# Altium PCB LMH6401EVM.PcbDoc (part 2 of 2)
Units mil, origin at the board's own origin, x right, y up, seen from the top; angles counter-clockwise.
Board outline 1307 x 2660 mil, 6 copper layers (Top Layer L1, Layer 2 GND L2, Layer 3 V+ L3, Layer 4 V- L4, Layer 5 GND L5, Bottom Layer L6), stack 56.6 mil thick; 69 components, 33 nets, 203 pads, 373 vias.
Unrouted connection lines stored in the file: 2.
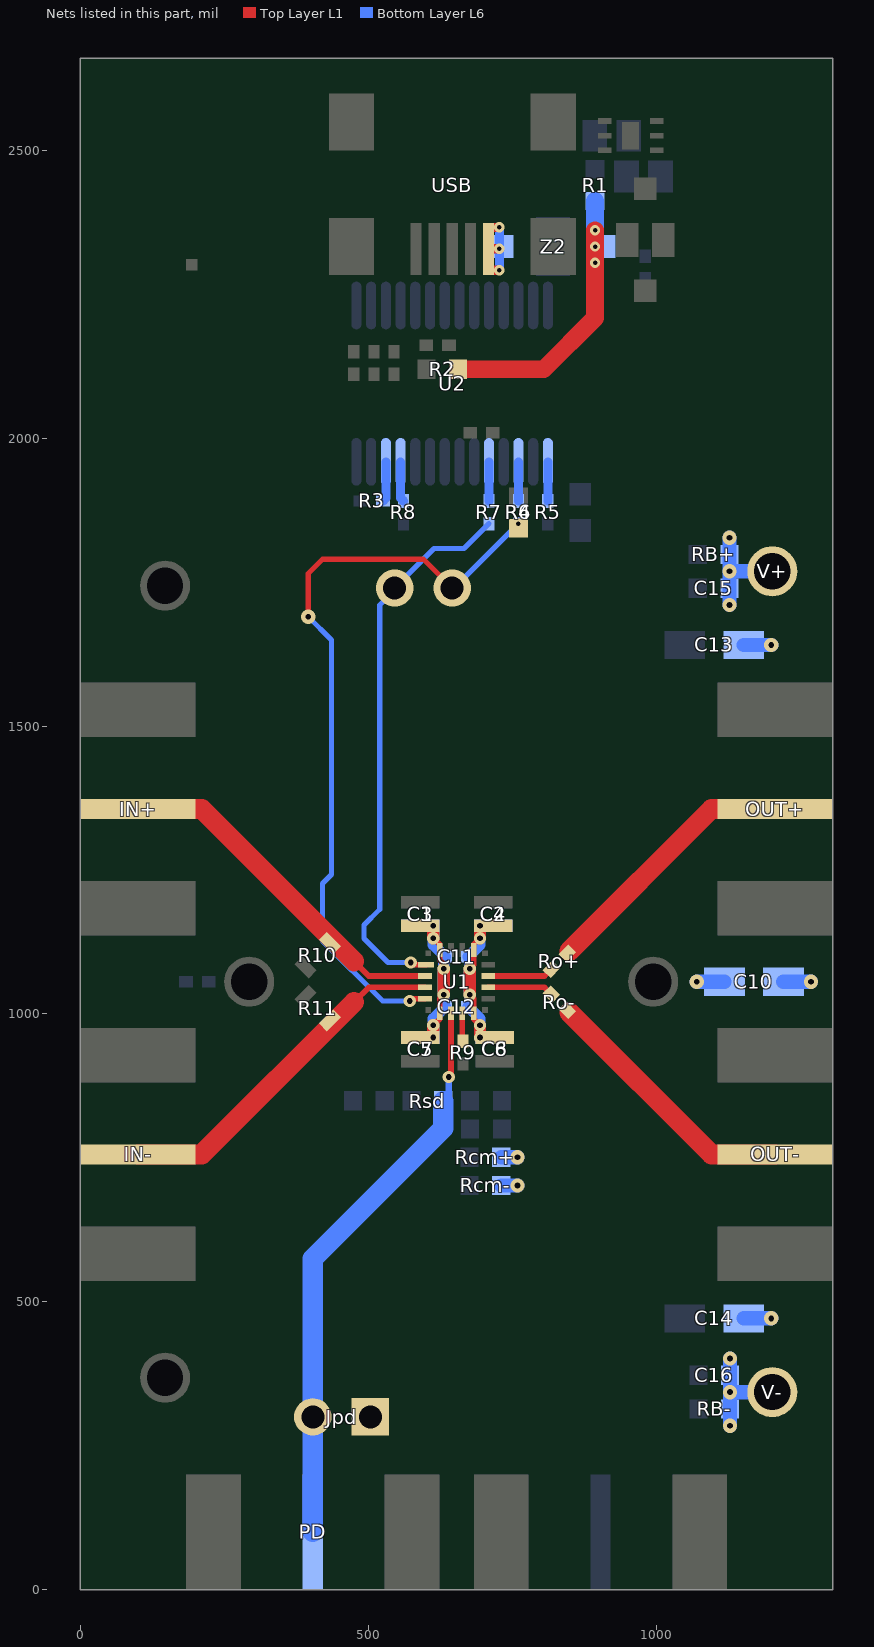
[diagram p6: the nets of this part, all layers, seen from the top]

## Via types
v1: diameter 25, hole 10, Top Layer L1 to Bottom Layer L6, tented both sides, 221 vias
v2: diameter 18, hole 8, Top Layer L1 to Bottom Layer L6, tented top, 73 vias
v3: diameter 18, hole 8, Top Layer L1 to Bottom Layer L6, tented both sides, 52 vias
v4: diameter 21.46, hole 10, Top Layer L1 to Bottom Layer L6, tented both sides, 22 vias
v5: diameter 64.96, hole 40, Top Layer L1 to Bottom Layer L6, 5 vias

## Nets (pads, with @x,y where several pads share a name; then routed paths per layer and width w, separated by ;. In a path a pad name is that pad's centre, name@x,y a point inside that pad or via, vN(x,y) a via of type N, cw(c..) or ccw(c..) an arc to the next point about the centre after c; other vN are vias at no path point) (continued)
NetIN+_1: IN+.1 R10.2 U1.2 | length 618.7
  Top Layer L1 w9.84: 475.26,1091.42 500.84,1065.84 U1.2@598.48,1065.84
  Top Layer L1 w35: IN+.1@100,1356 210.68,1356 475.26,1091.42
NetIN-_1: IN-.1 R11.1 U1.3 | length 618.7
  Top Layer L1 w9.84: 475.26,1020.58 500.84,1046.16 U1.3@598.48,1046.16
  Top Layer L1 w35: IN-.1@100,756 210.68,756 475.26,1020.58
NetJpd_2: Jpd.2 PD.1 Rsd.2 U1.6 | length 1000.4
  Top Layer L1 w9.84: v4(639.79,890.52) 643.76,894.49 U1.6@643.76,1000.88
  Bottom Layer L6 w12: Rsd.2@630.27,849 639.79,858.53 v4(639.79,890.52)
  Bottom Layer L6 w35: PD.1@403.6,100 403.6,574.6 630.27,801.26 Rsd.2@630.27,849
NetOUT+_1: OUT+.1 Ro+.2 | length 459.1
  Top Layer L1 w35: Ro+.2@849.92,1109.6 1096.32,1356 OUT+.1@1207,1356
NetOUT-_1: OUT-.1 Ro-.2 | length 459.1
  Top Layer L1 w35: Ro-.2@849.92,1002.4 1096.32,756 OUT-.1@1207,756
NetR1_2: R1.2 R2.1 Z2.1 | length 535
  Top Layer L1 w31: R2.1@656.09,2120 805,2120 894.03,2209.03 v3(894.03,2361.63)
  Bottom Layer L6 w31: v3(894.03,2304.83) R1.2@894.03,2412.44
  other v3: 894.03,2333.23
NetR3_1: R3.1 U2.12 | length 70.1
  Bottom Layer L6 w16: R3.1@525.59,1891.18 530.59,1896.18 U2.12@530.59,1959.17
NetR5_2: R5.2 U2.1 | length 68
  Bottom Layer L6 w16: R5.2@812.09,1891.18 U2.1@812.09,1959.17
NetR6_2: R6.2 U2.3 | length 68
  Bottom Layer L6 w16: R6.2@760.91,1891.18 U2.3@760.91,1959.17
NetR7_2: R7.2 U2.5 | length 68
  Bottom Layer L6 w16: R7.2@709.72,1891.18 U2.5@709.72,1959.17
NetR8_2: R8.2 U2.11 | length 70.1
  Bottom Layer L6 w16: U2.11@556.18,1959.17 556.18,1896.18 R8.2@561.18,1891.18
NetR9_2: R9.2 U1.7 | length 48.6
  Top Layer L1 w10: U1.7@663.45,1000.88 663.45,953.74 R9.2@664.5,952.69
NetRo+_1: Ro+.1 U1.11 | length 114.2
  Top Layer L1 w9.84: U1.11@708.72,1065.84 806.16,1065.84 Ro+.1@818.01,1077.69
NetRo-_1: Ro-.1 U1.10 | length 114.2
  Top Layer L1 w9.84: U1.10@708.72,1046.16 806.16,1046.16 Ro-.1@818.01,1034.31
NetUSB_1: USB.1 Z2.3 | length 205.6
  Top Layer L1 w16: v3(727.83,2292.02) 708.99,2292.02 USB.1@708.99,2329.29 ; v3(727.83,2329.29) USB.1@708.99,2329.29 ; v3(727.83,2366.57) 708.99,2366.57 USB.1@708.99,2329.29
  Bottom Layer L6 w16: v3(727.83,2292.02) v3(727.83,2329.29) v3(727.83,2366.57)
SDI: R7.1 U1.1 | length 964
  Top Layer L1 w9.84: v4(573.97,1089.5) 577.94,1085.53 U1.1@600.45,1085.53
  Bottom Layer L6 w9: v5@545.75,1736.38 520,1710.63 520,1182 492.75,1154.75 492.75,1131.25 534.5,1089.5 v4(573.97,1089.5) ; v5(545.75,1740) 614.25,1808.5 666.41,1808.5 R7.1@709.72,1851.81
SDO: R4.1 R6.1 U1.4 | length 1323
  Top Layer L1 w9: v1(395.75,1690) 395.75,1765 420.75,1790 595.75,1790 v5(645.75,1740)
  Top Layer L1 w9.84: v4(572,1022.5) 575.97,1026.47 U1.4@598.48,1026.47
  Bottom Layer L6 w9: v1(395.75,1690) 436,1649.75 436,1242 420.75,1226.75 420.75,1126.76 525,1022.5 v4(572,1022.5) ; v5@649.09,1740 v3(760.91,1851.81)
V+: C2.1 C4.2 C6.2 C8.1 C10.1 C11.2 C12.2 C13.1 C15.1 Jpd.1 RB+.2 Rcm+.2 U1.8 U1.13 V+.1 | length 806.2
  Top Layer L1 w9.84: v4(676.13,1033.47) 683.13,1026.47 U1.8@683.13,1000.88 683.13,991.37 v4(694.1,980.4) ; v4(676.13,1078.53) 683.13,1085.53 U1.13@683.13,1111.12 683.13,1120.63 v4(694.1,1131.6)
  Top Layer L1 w21.46: v4(676.13,1033.47) v4(676.13,1078.53) ; C6.2@694.1,959.02 v4(694.1,980.4) ; v4(694.1,1131.6) 694.1,1152.98 C4.2@716.87,1152.98
  Bottom Layer L6 w19.68: v4(676.13,1033.47) 676.13,1015.74 C12.2@673.29,1012.9 694.1,992.09 v4(694.1,980.4) ; v4(676.13,1078.53) 676.13,1096.26 C11.2@673.29,1099.1 694.1,1119.91 v4(694.1,1131.6)
  Bottom Layer L6 w21.46: v4(676.13,1033.47) v4(676.13,1078.53) ; v4(694.1,958.94) C8.1@716.87,958.94 ; C8.1@694.1,959.02 v4(694.1,980.4) ; v4(694.1,1131.6) 694.1,1152.98 C2.1@716.87,1152.98
  Bottom Layer L6 w25: Rcm+.2@731.06,751 v1(759.31,751) ; v1(1070.89,1056) C10.1@1118.82,1056 ; v1(1127.56,1710.54) v1(1127.56,1769) ; v1(1127.56,1827.46) RB+.2@1127.56,1798.23 v1(1127.56,1769) ; C13.1@1152.18,1641 v1(1200.11,1641) ; V+.1@1202,1769 v1(1127.56,1769)
  other v4: 694.1,1153.06
V-: C1.2 C3.1 C5.1 C7.2 C10.2 C11.1 C12.1 C14.2 C16.1 RB-.1 Rcm-.1 U1.5 U1.16 V-.1 | length 828.9
  Top Layer L1 w9.84: v4(613.11,980.4) 624.08,991.37 U1.5@624.08,1000.88 624.08,1026.47 v4(631.08,1033.47) ; v4(613.11,1131.6) 624.08,1120.63 U1.16@624.08,1111.12 624.08,1093.61 631.08,1086.61 v4(631.08,1078.53)
  Top Layer L1 w21.46: C5.1@590.34,959.02 613.11,959.02 v4(613.11,980.4) ; C3.1@590.34,1152.98 613.11,1152.98 v4(613.11,1131.6) ; v4(631.08,1033.47) v4(631.08,1078.53)
  Bottom Layer L6 w19.68: v4(613.11,980.4) 613.11,992.09 C12.1@633.92,1012.9 631.08,1015.74 v4(631.08,1033.47) ; v4(613.11,1131.6) 613.11,1119.91 C11.1@633.92,1099.1 631.08,1096.26 v4(631.08,1078.53)
  Bottom Layer L6 w21.46: C7.2@590.34,959.02 613.11,959.02 v4(613.11,980.4) ; C1.2@590.34,1152.98 613.11,1152.98 v4(613.11,1131.6) ; v4(631.08,1033.47) v4(631.08,1078.53)
  Bottom Layer L6 w25: Rcm-.1@731.06,702 v1(759.31,702) ; v1(1128.56,284.54) RB-.1@1128.56,313.77 v1(1128.56,343) ; v1(1128.56,401.46) C16.1@1128.56,372.23 v1(1128.56,343) ; C14.2@1152.18,471 v1(1200.11,471) ; V-.1@1203,343 v1(1128.56,343) ; C10.2@1221.18,1056 v1(1269.11,1056)
  other v4: 613.11,958.94 613.11,1153.06
pads on no net: U1. U2.2 U2.6 U2.8 U2.9 U2.10 U2.13 U2.14 U2.19 U2.22 U2.23 U2.24 U2.27 U2.28 U3.2 U3.5 USB.4

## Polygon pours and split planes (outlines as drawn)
GND2 on Top Layer L1 "Top Layer L1-GND2" (solid, pour order 8): 1307,2660 1307,1879 0,1879 0,2660
GND on Top Layer L1 "Top Layer L1-GND" (solid, remove dead copper, pour order 6): 0,0 0,1860 1307,1860 1307,0
GND on Bottom Layer L6 "Bottom Layer L6-GND" (solid, remove dead copper, pour order 5): 0,0 0,1860 1307,1860 1307,0
GND2 on Bottom Layer L6 "Bottom Layer L6-GND2" (solid, pour order 7): 1307,2660 1307,1879 0,1879 0,2660
GND2 on Layer 2 GND L2 (split plane): 1306.95,1879.08 0.05,1879.08 0.05,2659.95 1306.95,2659.95
GND on Layer 2 GND L2 (split plane): 1306.95,0.05 0.05,0.05 0.05,1859.92 1306.95,1859.92
NetC19_2 on Layer 3 V+ L3 (split plane): 1286.9,1879.08 20.1,1879.08 20.1,2639.9 1286.9,2639.9
V+ on Layer 3 V+ L3 (split plane): 1286.9,20.1 20.1,20.1 20.1,1859.92 1286.9,1859.92
GND2 on Layer 4 V- L4 (split plane): 1286.9,1879.08 20.1,1879.08 20.1,2639.9 1286.9,2639.9
V- on Layer 4 V- L4 (split plane): 1286.9,20.1 20.1,20.1 20.1,1859.92 1286.9,1859.92
GND2 on Layer 5 GND L5 (split plane): 1306.95,1879.08 0.05,1879.08 0.05,2659.95 1306.95,2659.95
GND on Layer 5 GND L5 (split plane): 1306.95,0.05 0.05,0.05 0.05,1859.92 1306.95,1859.92

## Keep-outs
Keep-Out Layer:
  text ".Layer_Name" at 577,-858.49 h60

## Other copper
Top Layer L1:
  text ".Layer_Name" at 577,-858.49 h60
Bottom Layer L6:
  text ".Layer_Name" at 577,-858.49 h60
Layer 2 GND L2 (plane layer: these items are gaps in the copper):
  lines w19: 0,1869.5 1307,1869.5
  text ".Layer_Name" at 577,-858.49 h60
Layer 5 GND L5 (plane layer: these items are gaps in the copper):
  lines w19: 0,1869.5 1307,1869.5
  text ".Layer_Name" at 577,-858.49 h60
Layer 3 V+ L3 (plane layer: these items are gaps in the copper):
  lines w19: 0,1869.5 1307,1869.5
  text ".Layer_Name" at 577,-858.49 h60
Layer 4 V- L4 (plane layer: these items are gaps in the copper):
  lines w19: 0,1869.5 1307,1869.5
  text ".Layer_Name" at 577,-858.49 h60

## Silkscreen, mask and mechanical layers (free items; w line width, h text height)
Top Overlay:
  region: 1072,504.99 772,504.99 772,404.99 1072,404.99
  text "GND" at 865,1585 h40 r90
  text "*CS" at 465,1575 h40 r90
  text "SDI" at 565,1575 h40 r90
  text "SDO" at 665,1575 h40 r90
  text "CLK" at 765,1575 h40 r90
  text ".PRJ_Title" at 372,550 h50
  text ".PRJ_Number" at 372,425 h40
  text ".PCB_Rev" at 662,425 h40
  text "-" at 732,425 h40
  text ".Layer_Name" at 577,-858.49 h60
Bottom Overlay:
  text "UL94V-0" at 1162,1975 h60 r270
  text "MADE IN U.S." at 162,1925 h60 r270
  text "TI" at 321.97,354 h60
  text ".CopyrightYear" at 597.97,354 h60
  text "©" at 714.97,350.48 h105
  text ".Layer_Name" at 577,-858.49 h60
Top Paste:
  text ".Layer_Name" at 577,-858.49 h60
Bottom Paste:
  text ".Layer_Name" at 577,-858.49 h60
Top Solder:
  lines w14.7: 475.26,1020.58 500.84,1046.16 598.48,1046.16 ; 475.26,1091.42 500.84,1065.84 598.48,1065.84 ; 708.72,1046.16 806.16,1046.16 818.01,1034.31 ; 708.72,1065.84 806.16,1065.84 818.01,1077.69
  lines w41: 100,756 210.36,756 474.94,1020.58 ; 100,1356 210.36,1356 474.94,1091.42 ; 849.92,1002.4 1096.32,756 1207,756 ; 849.92,1109.6 1096.32,1356 1207,1356
  lines w65: 0,1869.5 701,1869.5 ; 820,1869.5 1307,1869.5
  text ".Layer_Name" at 577,-858.49 h60
  text ".Layer_Name" at 577,-858.49 h60
Bottom Solder:
  lines w65: 0,1869.5 432,1869.5 ; 932,1869.5 1307,1869.5
  text ".Layer_Name" at 577,-858.49 h60
Drill Guide:
  text ".Layer_Name" at 577,-858.49 h60
M1 Board Outline:
  the board outline again, w10
  text ".Layer_Name" at 577,-858.49 h60
M2 Board Dimensions:
  rectangle: 124.5,-410.5 499.5,-285.5
  rectangle: -0.5,-285.5 124.5,-160.5
  lines w7: -0.5,-285.5 999.5,-285.5 ; 124.5,-410.5 124.5,-160.5 ; 249.5,-410.5 249.5,-160.5 ; 499.5,-410.5 499.5,-160.5 ; 749.5,-410.5 749.5,-160.5 ; -0.5,-410.5 -0.5,-160.5 999.5,-160.5 999.5,-410.5 -0.5,-410.5
  lines w10: -0.5,-475.5 -0.5,-455.5 ; 59.5,-485.5 -0.5,-465.5 ; 59.5,-445.5 -0.5,-465.5 ; 223.58,-465.5 -0.5,-465.5 ; 775.42,-465.5 999.5,-465.5 ; 939.5,-485.5 999.5,-465.5 ; 939.5,-445.5 999.5,-465.5 ; 999.5,-475.5 999.5,-455.5
  text "1000 (mil)" at 233.58,-501.49 h60
  text ".Layer_Name" at 577,-858.49 h60
M3 3D STEP Top:
  text ".Layer_Name" at 577,-858.49 h60
M4 3D STEP Bottom:
  text ".Layer_Name" at 577,-858.49 h60
M5 Assembly Top:
  lines w10: -292,-930.17 6308,-930.17 ; -292,-726.83 6310,-726.83 ; -292,-523.5 -292,-1133.5 3713,-1133.5 6310,-1133.5 6310,-523.5 -291.5,-523.5 -291.5,-1133.5 1284,-1133.5 ; 2173,-1133.5 2173,-523.5 ; 3440,-726.83 3440,-523.5 ; 4280,-726.83 4280,-523.5 ; 4902,-1140 4902,-937.17
  text "COMPONENTS MARKED 'DNP' SHOULD NOT BE POPULATED." at 1153.5,-318.5 h60
  text "ASSEMBLY VARIANT:" at 1153,-434 h60
  text ".VariantName" at 2189,-434 h60
  text "PCB VIEWED FROM TOP SIDE" at -228.5,-655.67 h60
  text "BOARD #:" at 2248,-655.67 h60
  text ".PRJ_Number" at 2793.5,-655.67 h60
  text "REV:" at 3638,-655.67 h60
  text ".PCB_Rev" at 3929.5,-655.67 h60
  text "SVN REV:" at 4476,-655.67 h60
  text ".VersionControl_RevNumber" at 4982,-655.67 h60
  text "IGNORE ->" at -228.5,-858.49 h60
  text "PLOT NAME =" at -228.5,-1064.34 h60
  text ".plot_File_Name" at 577,-1064.34 h60
  text "GENERATED    :" at 2250,-1064.34 h60
  text ".Print_Date" at 3119.5,-1064.34 h60
  text ".Print_Time" at 3848.5,-1064.34 h60
  text "TEXAS INSTRUMENTS" at 5113,-1064.34 h60
M6 Assembly Bottom:
  lines w10: -292.5,-727.33 6309.5,-727.33 ; -290.5,-930.67 6309.5,-930.67 ; 1115.5,-1140.5 1115.5,-937.67 ; 1737.5,-727.33 1737.5,-524 ; 2577.5,-727.33 2577.5,-524 ; 3844.5,-1134 3844.5,-524 ; 4733.5,-1134 6309,-1134 6309,-524 -292.5,-524 -292.5,-1134 2304.5,-1134 6309.5,-1134 6309.5,-524
  text "COMPONENTS MARKED 'DNP' SHOULD NOT BE POPULATED." at 6102,-318 h60
  text ".VariantName" at 5058,-434 h60
  text "ASSEMBLY VARIANT:" at 6097,-434 h60
  text ".VersionControl_RevNumber" at 1035.5,-656.17 h60
  text "SVN REV:" at 1541.5,-656.17 h60
  text ".PCB_Rev" at 2088,-656.17 h60
  text "REV:" at 2379.5,-656.17 h60
  text ".PRJ_Number" at 3224,-656.17 h60
  text "BOARD #:" at 3769.5,-656.17 h60
  text "PCB VIEWED FROM BOTTOM SIDE" at 6246,-656.17 h60
  text "IGNORE ->" at 2547.85,-858.49 h60
  text "TEXAS INSTRUMENTS" at 904.5,-1064.84 h60
  text ".Print_Time" at 2169,-1064.84 h60
  text ".Print_Date" at 2898,-1064.84 h60
  text "GENERATED    :" at 3767.5,-1064.84 h60
  text ".plot_File_Name" at 5440.5,-1064.84 h60
  text "PLOT NAME =" at 6246,-1064.84 h60
M9 Title Sheet:
  drawing of 57 lines, arcs and shapes, not listed
  text "1" at 739.84,8036.5 h70
  text "2" at 3235.5,8036.5 h70
  text "3" at 5724.84,8036.5 h70
  text "4" at 8231.51,8036.5 h70
  text "5" at 10730.5,8036.5 h70
  text "6" at 13235.5,8036.5 h70
  text "A" at -416.5,6893.5 h70
  text "A" at 14383.5,6893.5 h70
  text "B" at -416.5,4513.5 h70
  text "B" at 14383.5,4513.5 h70
  text "C" at -416.5,2138.5 h70
  text "C" at 14383.5,2138.5 h70
  text "PROJECT TITLE:" at 11343.5,277.5 h45
  text ".PRJ_Title" at 11393.5,144.17 h70
  text "DESIGNED FOR:" at 11343.5,-23.5 h45
  text ".PRJ_Customer" at 11393.5,-163.5 h70
  text "D" at -416.5,-231.5 h70
  text "D" at 14383.5,-231.5 h70
  text "FILE NAME:" at 11343.5,-323.5 h45
  text ".PCB_File_Name_No_Path" at 11393.5,-443.5 h70
  text "Texas Instruments (TI) and/or its licensors do not warrant the accuracy or completeness of this specification" at 6374,-605.34 h45
  text "ENGINEER:" at 11343.5,-613.5 h45
  text "LAYOUT BY:" at 12848.5,-613.5 h45
  text "or any information contained therein. TI and/or its licensors do not warrant that this design will meet" at 6329.01,-718 h45
  text ".PRJ_Engineer" at 11393.5,-768.49 h70
  text ".PCB_Layout" at 12899,-768.49 h70
  text "the specifications, will be suitable for your application or fit for any particular purpose, or will operate in" at 6329.01,-830.67 h45
  text ".Layer_Name" at 577,-858.49 h60
  text "ALTIUM DESIGNER VERSION:" at 12848.5,-923.5 h45
  text "an implementation. TI and/or its licensors do not warrant that the design is production worthy. You should" at 6329.01,-943.33 h45
  text "completely validate and test your design implementation to confirm the system functionality for your application." at 6374,-1056 h45
  text ".print_Scale" at 11393.5,-1056.83 h70
  text ".Application_BuildNumber" at 12899,-1056.83 h70
  text "1" at 739.84,-1263.5 h70
  text "2" at 3235.5,-1263.5 h70
  text "3" at 5724.84,-1263.5 h70
  text "4" at 8231.51,-1263.5 h70
  text "5" at 10730.5,-1263.5 h70
  text "6" at 13235.5,-1263.5 h70
M10 Fab Notes:
  drawing of 212 lines, arcs and shapes, not listed
  text "DESIGN INFORMATION" at 12381.02,6810 h60
  text "(REFER ALSO ARRAY/PANEL PROFILING INFORMATION)" at 12019.46,6648.29 h60
  text "BOARD SIZE" at 11333.46,6644 h60
  text "X" at 12301.46,6516.18 h60
  text "Number of Layers :" at 11736.46,6319 h60
  text "6" at 12831.27,6309 h60
  text "MIN. TRACK WIDTH:" at 11736.46,6180 h60
  text "8" at 12832.7,6180 h60
  text "MIL" at 12987.46,6180 h60
  text "MIN. CLEARANCE:" at 11736.46,6048 h60
  text "8" at 12832.7,6048 h60
  text "MIL" at 12987.46,6048 h60
  text "MIN. VIA PAD SIZE:" at 11736.46,5916 h60
  text "21" at 12802.71,5916 h60
  text "MIL" at 12987.46,5916 h60
  text "0.05mm (2MIL)" at 12431.46,5774.29 h60
  text "MINIMUM ANNULAR RING" at 11407.23,5770 h60
  text "EXTERNAL" at 13139.46,5770 h60
  text "PER" at 11607.23,5652 h60
  text "IPC-D-275 CLASS 2 LEVEL C" at 11827.23,5652 h60
  text "MIL, HOLES" at 13315.46,5539.71 h60
  text "+/-" at 12923,5539 h60
  text "+/-" at 13777,5539 h60
  text "REGISTRATION TOLERANCES:" at 11407.23,5534 h60
  text "METAL" at 12607,5534 h60
  text "5" at 13183.2,5534 h60
  text "3" at 14016.2,5534 h60
  text "MIL" at 14132.46,5534 h60
  text "MATERIAL:" at 11332.46,5324.54 h60
  text "FR-4 High Tg" at 12318.9,5184.21 h60
  text "FR-408" at 11753.46,5175.64 h60
  text "X" at 12165.46,5175.64 h60
  text "X" at 13054.46,5176 h60
  text "OTHER   ROGERS 4350" at 13241.46,5175.64 h60
  text "62 MIL (1.6mm) +/-10%" at 12073.56,5012.92 h60
  text "THICKNESS:" at 11407.23,5008.64 h60
  text "X" at 11945.4,5008.64 h60
  text "OTHER" at 13358.46,5008.64 h60
  text "TOLERANCE:" at 11407.23,4850.64 h60
  text "X" at 12246.53,4850.64 h60
  text "ANSI IPC-6012 TYPE 3 CLASS 2" at 12433.48,4850.64 h60
  text "OTHER +/-" at 12433.46,4694.64 h60
  text "BOW & TWIST:" at 11407.23,4537.64 h60
  text "X" at 12246.53,4537.64 h60
  text "ANSI IPC-6012 TYPE 3 CLASS 2" at 12433.48,4537.64 h60
  text "OTHER +/-" at 12433.46,4379.13 h60
  text "COPPER THICKNESS (FINISHED):" at 11332.46,4243.64 h60
  text "1.4MIL (1oz)" at 12212.46,4090.92 h60
  text "2MIL (1.4oz)" at 12979.46,4090.92 h60
  text "2.8MIL (2oz)" at 13706.46,4090.92 h60
  text "OUTER:" at 11689.46,4086.64 h60
  text "X" at 12084,4086 h60
  text "1.4MIL (1oz)" at 12212.46,3933.92 h60
  text "2.8MIL (2oz)" at 12979.46,3933.92 h60
  text "N/A" at 13706,3934.29 h60
  text "INNER SIGNAL:" at 11400.38,3929.64 h60
  text "X" at 12085.42,3929.64 h60
  text "DRILLING:" at 11332.46,3790.64 h60
  text "REFERENCE:" at 11407.23,3673.64 h60
  text "X" at 12055.46,3673.64 h60
  text "AS SHOWN" at 12242.46,3673.64 h60
  text "X" at 12956.46,3673.64 h60
  text "NC_DRILL FILES" at 13093.46,3673.64 h60
  text "PTH MIN COPPER THICKNESS:" at 11407.23,3515.64 h60
  text "X" at 12757.46,3515.64 h60
  text "1MIL" at 12894.46,3515.64 h60
  text "OTHER" at 13391.46,3515.64 h60
  text "BOARD FINISH:" at 11332.46,3356.64 h60
  text "SILKSCREEN:" at 11487.68,3238.64 h60
  text "X" at 12436.46,3238.64 h60
  text "TOP" at 12562.46,3238.64 h60
  text "X" at 12946.46,3238.64 h60
  text "BOTTOM" at 13073.46,3238.64 h60
  text "SILKSCREEN COLOR:" at 11487.68,3071.64 h60
  text "X" at 12435.42,3071.64 h60
  text "WHITE" at 12562.46,3071.64 h60
  text "OTHER" at 13073.46,3071.64 h60
  text "SOLDER RESIST COLOR:" at 11487.68,2901.64 h60
  text "X" at 12055.42,2742.44 h60
  text "GREEN" at 12182.46,2742.44 h60
  text "BLUE" at 12773.46,2742.44 h60
  text "OTHER" at 13311.46,2742.44 h60
  text "IMMERSION GOLD (ENIG)" at 12393.46,2553.92 h60
  text "ENEPIG" at 13731,2550.64 h60
  text "SURFACE FINISH:" at 11332.46,2549.64 h60
  text "X" at 12206.51,2549.64 h60
  text "IMM. TIN/SILVER OR EQUIV" at 11662,2392.64 h60
  text "OTHER" at 13093.46,2392.64 h60
  text "ARRAY/PANEL:" at 11332.46,2213.64 h60
  text "CUT AND TRIM PER MECH LAYER 1" at 12393.46,2209.35 h60
  text "N.C. ROUTE" at 12393.46,2057.64 h60
  text "X" at 13072.46,2057.64 h60
  text "V. SCORE" at 13259.46,2057.64 h60
  text "CERTIFICATION:" at 11332.46,1920.64 h60
  text "MATERIALS AND WORKMANSHIP FOR ALL PCBS" at 12057.46,1920.64 h60
  text "TO MEET OR EXCEED THE REQUIREMENTS OF:" at 12057.46,1822.64 h60
  text "Single ended tracks 50 ohms Top Layer equal 35mils width." at 3833,1820 h100
  text "X" at 11683.96,1686.13 h60
  text "ANSI IPC-A-600F CLASS ->" at 11822.96,1686.13 h60
  text "X" at 13462.02,1686.13 h60
  text "2" at 13580.96,1686.14 h60
  text "1" at 13265.96,1684.64 h60
  text "3" at 13934.96,1684.64 h60
  text "X" at 11686.02,1526.64 h60
  text "UL 94V-0" at 11822.96,1526.64 h60
  text "X" at 12498.02,1526.64 h60
  text "RoHS" at 12634.96,1526.64 h60
  text "OTHER" at 13279.36,1526.64 h60
  text "PER ORDER" at 13676.42,1526.64 h60
  text "ADDITIONAL REQUIREMENTS:" at 11332.46,1385.64 h60
  text "MICROSECTION:" at 11407.23,1270.64 h60
  text "YES" at 12312.96,1270.64 h60
  text "REQUIRED" at 13174.46,1114.49 h60
  text "BARE BOARD ELEC. TEST:" at 11407.23,1111.64 h60
  text "NONE" at 12712.96,1111.64 h60
  text "X" at 13047.46,1111.64 h60
  text "PER ORDER" at 13766.46,1111.64 h60
  text "MANUFACTURER'S UL:" at 11407.23,954.64 h60
  text "RAIL" at 12572.96,950.35 h60
  text "METAL" at 13064.77,950.35 h60
  text "X" at 13440,950 h60
  text "SILK" at 13576.46,950.35 h60
  text ".Layer_Name" at 577,-858.49 h60
M11 Gerber Information:
  lines w10: -292,-930.17 6308,-930.17 ; -292,-726.83 6310,-726.83 ; -292,-523.5 -292,-1133.5 3713,-1133.5 6310,-1133.5 6310,-523.5 -291.5,-523.5 -291.5,-1133.5 1284,-1133.5 ; 2173,-1133.5 2173,-523.5 ; 3440,-726.83 3440,-523.5 ; 4280,-726.83 4280,-523.5 ; 4902,-1140 4902,-937.17
  text "ALL ARTWORK VIEWED FROM TOP SIDE" at -228.5,-655.67 h60
  text "BOARD #:" at 2248,-655.67 h60
  text ".PRJ_Number" at 2793.5,-655.67 h60
  text "REV:" at 3638,-655.67 h60
  text ".PCB_Rev" at 3929.5,-655.67 h60
  text "SVN REV:" at 4476,-655.67 h60
  text ".VersionControl_RevNumber" at 4982,-655.67 h60
  text "LAYER NAME =" at -228.5,-858.49 h60
  text "PLOT NAME =" at -228.5,-1064.34 h60
  text ".plot_File_Name" at 577,-1064.34 h60
  text "GENERATED    :" at 2250,-1064.34 h60
  text ".Print_Date" at 3119.5,-1064.34 h60
  text ".Print_Time" at 3848.5,-1064.34 h60
  text "TEXAS INSTRUMENTS" at 5113,-1064.34 h60
M12 Stackup:
  lines w5: 11364,7753.1 14227,7753.1 ; 11364,7848.3 14227,7848.3 ; 11304,6980 ccw(c11335,6980) 11335,6949 14256,6949 ccw(c14256,6980) 14287,6980 14287,7920 ccw(c14256,7920) 14256,7951 11335,7951 ccw(c11335,7920) 11304,7920 11304,6980
  text "Layer Stack Up Detail for: LMH6401_rev_a.PcbDoc" at 11364,7870.95 h39
  text "Layer" at 11364,7812.8 h22
  text "Gerber" at 11975,7812.8 h22
  text "Copper" at 12286.16,7812.8 h22
  text "Dielectric" at 12633.24,7812.8 h22
  text "Dielectric" at 12995.72,7812.8 h22
  text "Dielectric" at 13451.76,7812.8 h22
  text "Dielectric" at 13814.24,7812.8 h22
  text "Name" at 11364,7768.8 h22
  text "Document" at 11975,7768.8 h22
  text "Thickness" at 12286.16,7768.8 h22
  text "Height" at 12633.24,7768.8 h22
  text "Material" at 12995.72,7768.8 h22
  text "Constant" at 13451.76,7768.8 h22
  text "Type" at 13814.24,7768.8 h22
  text "Top Solder Mask" at 11364,7706.76 h31
  text "(.GTS)" at 11975,7706.76 h31
  text "0.4mil" at 12633.24,7706.76 h31
  text "Solder Resist" at 12995.72,7706.76 h31
  text "3.50" at 13451.76,7706.76 h31
  text "Top Layer L1" at 11364,7619.09 h31
  text "(.GTL)" at 11975,7619.09 h31
  text "1.4mil" at 12286.16,7619.09 h31
  text "16.6mil" at 12633.24,7575.25 h31
  text "Rogers RO4350" at 12995.72,7575.25 h31
  text "3.66" at 13451.76,7575.25 h31
  text "Core" at 13814.24,7575.25 h31
  text "Layer 2 GND L2" at 11364,7531.41 h31
  text "(.GP1)" at 11975,7531.41 h31
  text "1.4mil" at 12286.16,7531.41 h31
  text "5mil" at 12633.24,7487.58 h31
  text "FR406" at 12995.72,7487.58 h31
  text "4.80" at 13451.76,7487.58 h31
  text "PrePreg" at 13814.24,7487.58 h31
  text "Layer 3 V+ L3" at 11364,7443.74 h31
  text "(.GP2)" at 11975,7443.74 h31
  text "1.4mil" at 12286.16,7443.74 h31
  text "5mil" at 12633.24,7399.9 h31
  text "FR406" at 12995.72,7399.9 h31
  text "4.80" at 13451.76,7399.9 h31
  text "Core" at 13814.24,7399.9 h31
  text "Layer 4 V- L4" at 11364,7356.06 h31
  text "(.GP3)" at 11975,7356.06 h31
  text "1.4mil" at 12286.16,7356.06 h31
  text "5mil" at 12633.24,7312.23 h31
  text "FR406" at 12995.72,7312.23 h31
  text "4.80" at 13451.76,7312.23 h31
  text "PrePreg" at 13814.24,7312.23 h31
  text "Layer 5 GND L5" at 11364,7268.39 h31
  text "(.GP4)" at 11975,7268.39 h31
  text "1.4mil" at 12286.16,7268.39 h31
  text "16.6mil" at 12633.24,7224.55 h31
  text "FR406" at 12995.72,7224.55 h31
  text "4.80" at 13451.76,7224.55 h31
  text "Core" at 13814.24,7224.55 h31
  text "Bottom Layer L6" at 11364,7180.71 h31
  text "(.GBL)" at 11975,7180.71 h31
  text "1.4mil" at 12286.16,7180.71 h31
  text "Bottom Solder Mask" at 11364,7093.04 h31
  text "(.GBS)" at 11975,7093.04 h31
  text "0.4mil" at 12633.24,7093.04 h31
  text "Solder Resist" at 12995.72,7093.04 h31
  text "3.50" at 13451.76,7093.04 h31
  text ".Layer_Name" at 577,-858.49 h60
M13 Component Bodies Top:
  text ".Layer_Name" at 577,-858.49 h60
M14 Component Bodies Bottom:
  text ".Layer_Name" at 577,-858.49 h60
M15 Courtyards Top:
  text ".Layer_Name" at 577,-858.49 h60
M16 Courtyards Bottom:
  text ".Layer_Name" at 577,-858.49 h60
Drill Drawing:
  text ".legend" at 5122.5,725.5 h60
  text "Drill Table" at 5147.5,540.5 h60
  text ".Layer_Name" at 577,-858.49 h60

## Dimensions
0,0 to 1307,0 on M2 Board Dimensions
0,0 to 0,2660 on M2 Board Dimensions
